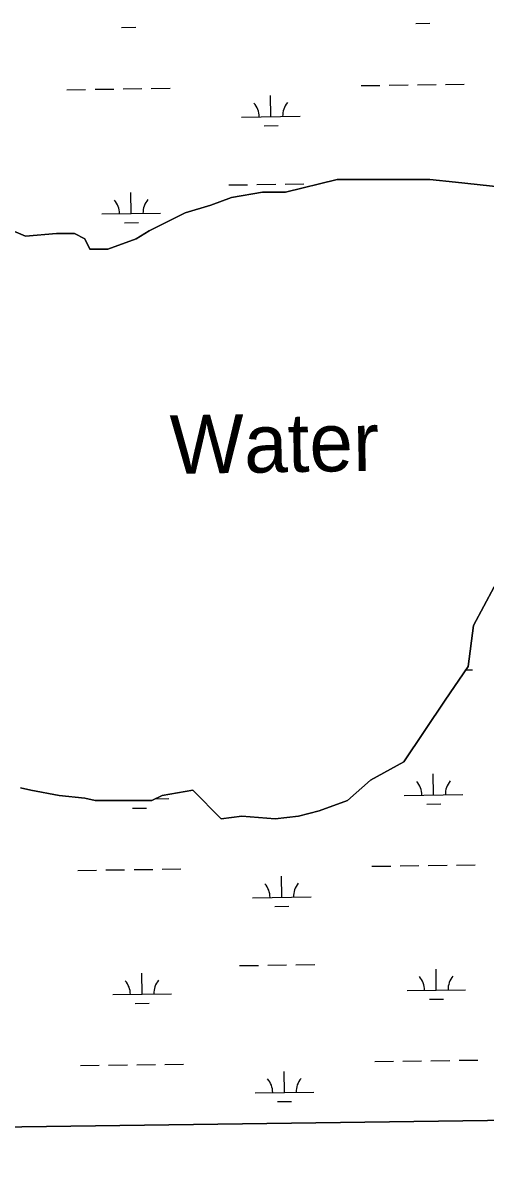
# Model space of a CAD drawing. Extents: x 3767014 to 3805179, y 361544 to 387384.
# Drawn here: x 3777264 to 3778054, y 366965 to 368930 of the extents above; entities that cross this region are included whole.
import ezdxf

# ---------------------------------------------------------------- set-up
doc = ezdxf.new("R2010")
doc.units = 0
for name, color, linetype in [('V-GRID-FRAM', 7, 'Continuous'), ('V-RIVR-IDEN', 7, 'Continuous'), ('V-TOPO-SHOR', 7, 'Continuous'), ('V-WETL-SWMP', 7, 'Continuous')]:
    doc.layers.add(name, color=color, linetype=linetype)

msp = doc.modelspace()

# ---------------------------------------------------------------- linework, layer by layer
at = {"layer": 'V-GRID-FRAM'}
msp.add_lwpolyline([(3771006.872, 385146.094), (3802799.803, 385587.734), (3803060.286, 367407.215), (3771251.489, 366965.353), (3771006.872, 385146.094)], dxfattribs=at)
at = {"layer": 'V-TOPO-SHOR'}
for points in [[(3778080.51, 368650.544), (3778001.484, 368659.33), (3777957.581, 368663.723), (3777799.528, 368663.723), (3777711.721, 368641.758), (3777672.208, 368641.758), (3777619.524, 368632.972), (3777584.401, 368619.793), (3777540.498, 368606.614), (3777479.033, 368575.863), (3777457.081, 368562.684), (3777408.787, 368545.113), (3777378.055, 368545.113)], [(3777378.055, 368545.113), (3777369.274, 368562.684), (3777351.713, 368571.47), (3777320.98, 368571.47), (3777268.296, 368567.077), (3777237.564, 368580.256)], [(3777259.515, 367626.98), (3777277.077, 367622.587), (3777325.371, 367613.801), (3777369.274, 367609.408), (3777386.836, 367605.015), (3777483.423, 367605.015), (3777500.985, 367613.801), (3777553.669, 367622.587), (3777601.963, 367574.264), (3777637.085, 367578.657), (3777694.16, 367574.264), (3777733.673, 367578.657), (3777768.796, 367587.443), (3777817.09, 367605.015), (3777856.603, 367640.159), (3777913.677, 367670.91), (3777983.923, 367776.341), (3778023.436, 367833.45), (3778032.217, 367903.737), (3778067.339, 367969.632)]]:
    msp.add_lwpolyline(points, dxfattribs=at)
at = {"layer": 'V-WETL-SWMP'}
for p, q in [((3777432.112, 368922.643), (3777456.109, 368922.976)), ((3777933.971, 368929.614), (3777957.969, 368929.948)), ((3777338.73, 368816.696), (3777370.727, 368817.14)), ((3777386.726, 368817.362), (3777418.722, 368817.807)), ((3777434.721, 368818.029), (3777466.718, 368818.473)), ((3777482.716, 368818.696), (3777514.713, 368819.14)), ((3777840.59, 368823.667), (3777872.587, 368824.111)), ((3777888.585, 368824.334), (3777920.582, 368824.778)), ((3777936.581, 368825), (3777968.577, 368825.445)), ((3777984.576, 368825.667), (3778016.573, 368826.112)), ((3777686.717, 368770.783), (3777686.217, 368806.779)), ((3777636.722, 368770.088), (3777736.713, 368771.477)), ((3777674.933, 368755.186), (3777698.931, 368755.52)), ((3777710.911, 368655.676), (3777742.908, 368656.12)), ((3777711.721, 368641.758), (3777799.528, 368663.723)), ((3777799.528, 368663.723), (3777957.581, 368663.723)), ((3777957.581, 368663.723), (3778001.484, 368659.33)), ((3778001.484, 368659.33), (3778080.51, 368650.544)), ((3777448.517, 368605.596), (3777448.017, 368641.593)), ((3777614.92, 368654.342), (3777646.917, 368654.787)), ((3777619.524, 368632.972), (3777672.208, 368641.758)), ((3777662.915, 368655.009), (3777694.912, 368655.453)), ((3777672.208, 368641.758), (3777711.721, 368641.758)), ((3777540.498, 368606.614), (3777584.401, 368619.793)), ((3777584.401, 368619.793), (3777619.524, 368632.972)), ((3777398.522, 368604.902), (3777498.512, 368606.291)), ((3777479.033, 368575.863), (3777540.498, 368606.614)), ((3777237.564, 368580.256), (3777268.296, 368567.077)), ((3777436.732, 368590), (3777460.73, 368590.333)), ((3777268.296, 368567.077), (3777320.98, 368571.47)), ((3777320.98, 368571.47), (3777351.713, 368571.47)), ((3777351.713, 368571.47), (3777369.274, 368562.684)), ((3777369.274, 368562.684), (3777378.055, 368545.113)), ((3777408.787, 368545.113), (3777457.081, 368562.684)), ((3777457.081, 368562.684), (3777479.033, 368575.863)), ((3777378.055, 368545.113), (3777408.787, 368545.113)), ((3778067.339, 367969.632), (3778032.217, 367903.737)), ((3778032.217, 367903.737), (3778023.436, 367833.45)), ((3778023.436, 367833.45), (3777983.923, 367776.341)), ((3778019.688, 367828.034), (3778030.435, 367828.183)), ((3777983.923, 367776.341), (3777913.677, 367670.91)), ((3777913.677, 367670.91), (3777856.603, 367640.159)), ((3777856.603, 367640.159), (3777817.09, 367605.015)), ((3777964.239, 367614.639), (3777963.739, 367650.635)), ((3777277.077, 367622.587), (3777259.515, 367626.98)), ((3777325.371, 367613.801), (3777277.077, 367622.587)), ((3777553.669, 367622.587), (3777500.985, 367613.801)), ((3777601.963, 367574.264), (3777553.669, 367622.587)), ((3777914.244, 367613.944), (3778014.234, 367615.333)), ((3777369.274, 367609.408), (3777325.371, 367613.801)), ((3777386.836, 367605.015), (3777369.274, 367609.408)), ((3777483.423, 367605.015), (3777386.836, 367605.015)), ((3777500.985, 367613.801), (3777483.423, 367605.015)), ((3777489.477, 367608.044), (3777512.375, 367608.362)), ((3777817.09, 367605.015), (3777768.796, 367587.443)), ((3777952.454, 367599.043), (3777976.452, 367599.376)), ((3777450.595, 367592.071), (3777474.593, 367592.405)), ((3777637.085, 367578.657), (3777601.963, 367574.264)), ((3777694.16, 367574.264), (3777637.085, 367578.657)), ((3777733.673, 367578.657), (3777694.16, 367574.264)), ((3777768.796, 367587.443), (3777733.673, 367578.657)), ((3777357.213, 367486.124), (3777389.21, 367486.568)), ((3777405.209, 367486.791), (3777437.206, 367487.235)), ((3777453.204, 367487.457), (3777485.201, 367487.902)), ((3777501.2, 367488.124), (3777533.196, 367488.569)), ((3777859.073, 367493.095), (3777891.07, 367493.54)), ((3777907.068, 367493.762), (3777939.065, 367494.207)), ((3777955.064, 367494.429), (3777987.061, 367494.873)), ((3778003.059, 367495.095), (3778035.056, 367495.54)), ((3777705.201, 367440.211), (3777704.701, 367476.208)), ((3777655.206, 367439.516), (3777755.196, 367440.905)), ((3777693.416, 367424.615), (3777717.414, 367424.948)), ((3777633.403, 367323.77), (3777665.4, 367324.215)), ((3777681.399, 367324.437), (3777713.395, 367324.882)), ((3777729.394, 367325.104), (3777761.391, 367325.548)), ((3777467, 367275.024), (3777466.5, 367311.021)), ((3777968.86, 367281.996), (3777968.36, 367317.992)), ((3777918.865, 367281.301), (3778018.855, 367282.69)), ((3777417.005, 367274.33), (3777516.995, 367275.719)), ((3777957.075, 367266.4), (3777981.073, 367266.733)), ((3777455.216, 367259.428), (3777479.213, 367259.762)), ((3778007.68, 367162.453), (3778039.677, 367162.897)), ((3777361.834, 367153.481), (3777393.831, 367153.925)), ((3777409.83, 367154.148), (3777441.827, 367154.592)), ((3777457.825, 367154.814), (3777489.822, 367155.259)), ((3777505.82, 367155.481), (3777537.817, 367155.926)), ((3777709.822, 367107.568), (3777709.322, 367143.565)), ((3777863.694, 367160.452), (3777895.691, 367160.897)), ((3777911.689, 367161.119), (3777943.686, 367161.564)), ((3777959.685, 367161.786), (3777991.682, 367162.23)), ((3777659.826, 367106.874), (3777759.817, 367108.263)), ((3777698.037, 367091.972), (3777722.035, 367092.305)), ((3776941.544, 367044.395), (3779370.463, 367078.135))]:
    msp.add_line(p, q, dxfattribs=at)
for centre, start, end in [((3777631.473, 368770.49), 0.024037, 41.567696), ((3777741.948, 368772.025), 140.024034, 181.567693), ((3777393.273, 368605.304), 0.024037, 41.567696), ((3777503.748, 368606.838), 140.024034, 181.567693), ((3777908.995, 367614.346), 0.024037, 41.567696), ((3778019.47, 367615.881), 140.024034, 181.567693), ((3777649.957, 367439.918), 0.024037, 41.567696), ((3777760.432, 367441.453), 140.024034, 181.567693), ((3777913.616, 367281.703), 0.024037, 41.567696), ((3778024.091, 367283.238), 140.024034, 181.567693), ((3777411.756, 367274.732), 0.024037, 41.567696), ((3777522.231, 367276.267), 140.024034, 181.567693), ((3777654.577, 367107.276), 0.024037, 41.567696), ((3777765.053, 367108.81), 140.024034, 181.567693)]:
    msp.add_arc(centre, 35.246, start, end, dxfattribs=at)

# ---------------------------------------------------------------- texts
at = {"layer": 'V-RIVR-IDEN'}
msp.add_text('Water', height=100, rotation=0.948572, dxfattribs=at).set_placement((3777515.307, 368161.588))

doc.saveas('drawing.dxf')
